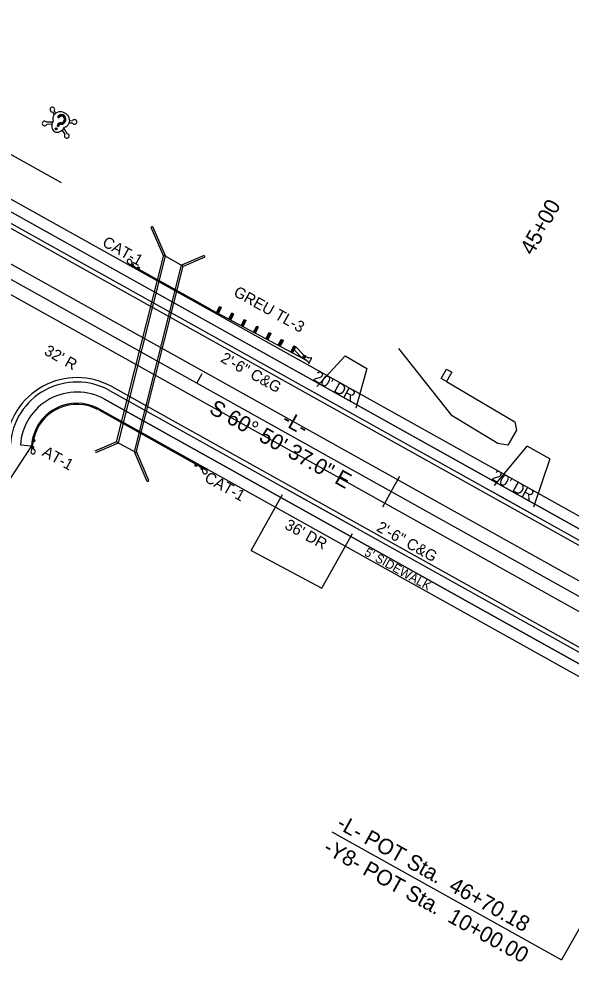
# Model space of a CAD drawing. Extents: x 1762196 to 1766326, y 709922 to 713142.
# Drawn here: x 1764729.9 to 1764978, y 710574.1 to 710998.1 of the extents above; entities that cross this region are included whole.
import ezdxf

# ---------------------------------------------------------------- set-up
doc = ezdxf.new("R2010")
doc.units = 0
for name, color, linetype in [('Culvert Barrel', 7, 'Continuous'), ('Culvert Wing', 7, 'Continuous'), ('Old_Level_20', 7, 'Continuous'), ('Old_Level_3', 7, 'Continuous'), ('Pattern 1', 7, 'Continuous'), ('Pattern 2', 7, 'Continuous'), ('Pattern 4', 7, 'Continuous'), ('Prop Conc 2ft 6in Curb and Gutter', 7, 'Continuous'), ('Prop Dimension', 7, 'Continuous'), ('Prop EOT', 7, 'Continuous'), ('Prop GRAU CAT1 Cell', 7, 'Continuous'), ('Prop Guardrail', 7, 'Continuous'), ('Prop Guardrail Anchor Unit CELL', 7, 'Continuous'), ('Prop Horizontal Alignment', 7, 'Continuous'), ('Prop Horizontal Alignment Direction Label', 7, 'Continuous'), ('Prop Horizontal Alignment Station Label', 7, 'Continuous'), ('Prop Horizontal Alignment Tick Label', 7, 'Continuous'), ('Prop Horizontal Alignment Tick Large', 7, 'Continuous'), ('Prop Horizontal Alignment Tick Small', 7, 'Continuous'), ('Prop Lane Lines', 7, 'Continuous')]:
    doc.layers.add(name, color=color, linetype=linetype)

msp = doc.modelspace()

# ---------------------------------------------------------------- linework, layer by layer
at = {"layer": 'Culvert Barrel'}
for p, q in [((1764773.88, 710808.01), (1764795.03, 710891.88)), ((1764774.63, 710807.59), (1764795.79, 710891.46)), ((1764795.03, 710891.88), (1764803.77, 710887)), ((1764781.87, 710803.55), (1764803.02, 710887.42)), ((1764782.62, 710803.13), (1764803.77, 710887)), ((1764773.88, 710808.01), (1764782.62, 710803.13))]:
    msp.add_line(p, q, dxfattribs=at)
at = {"layer": 'Culvert Wing'}
for p, q in [((1764790.04, 710904.77), (1764789.28, 710904.44)), ((1764789.28, 710904.44), (1764794.91, 710891.39)), ((1764790.04, 710904.77), (1764795.79, 710891.46)), ((1764813.12, 710891.78), (1764803.02, 710887.42)), ((1764813.45, 710891.02), (1764803.73, 710886.82)), ((1764813.45, 710891.02), (1764813.12, 710891.78)), ((1764764.2, 710803.99), (1764773.92, 710808.19)), ((1764764.53, 710803.23), (1764774.63, 710807.59)), ((1764787.61, 710790.24), (1764781.87, 710803.55)), ((1764788.38, 710790.57), (1764782.74, 710803.62)), ((1764787.61, 710790.24), (1764788.38, 710790.57))]:
    msp.add_line(p, q, dxfattribs=at)
at = {"layer": 'Old_Level_20'}
for p, q in [((1764924.57, 710819.74), (1764900.69, 710849.89)), ((1764922.09, 710835.18), (1764952.82, 710817)), ((1764945.07, 710807.21), (1764924.57, 710819.74)), ((1764952.82, 710817), (1764953.55, 710813.29)), ((1764953.55, 710813.29), (1764949.61, 710806.53)), ((1764949.61, 710806.53), (1764945.07, 710807.21))]:
    msp.add_line(p, q, dxfattribs=at)
msp.add_lwpolyline([(1764921.99, 710840.61), (1764924.38, 710839.28), (1764922.09, 710835.18), (1764919.7, 710836.51)], close=True, dxfattribs=at)
at = {"layer": 'Old_Level_3'}
for p, q in [((1764749.11, 710924.39), (1764725.72, 710937.41)), ((1764863.85, 710832.9), (1764876.5, 710846.73)), ((1764876.5, 710846.73), (1764886.23, 710840.99)), ((1764886.23, 710840.99), (1764881.32, 710823.15)), ((1764943.66, 710788.37), (1764958.3, 710805.99)), ((1764968.47, 710800.31), (1764958.3, 710805.99)), ((1764968.47, 710800.31), (1764961.13, 710778.63)), ((1764834.31, 710759.08), (1764848.37, 710784.28)), ((1764866.1, 710742.17), (1764879.81, 710766.74)), ((1764834.31, 710759.08), (1764866.1, 710742.17))]:
    msp.add_line(p, q, dxfattribs=at)
at = {"layer": 'Pattern 1'}
for p, q in [((1764581.02, 710998.13), (1765029.9, 710747.7)), ((1765022.41, 710746.16), (1764578.58, 710993.76)), ((1765087.39, 710649.22), (1764768.48, 710827.13)), ((1764766.04, 710822.76), (1765089.97, 710642.05)), ((1764730.61, 710806.6), (1764735.6, 710806.26))]:
    msp.add_line(p, q, dxfattribs=at)
for radius in [25.5, 20.5]:
    msp.add_arc((1764756.05, 710804.86), radius, 60.8436, 176.081, dxfattribs=at)
at = {"layer": 'Pattern 2'}
for p, q in [((1764581.02, 710998.13), (1765029.9, 710747.7)), ((1764578.58, 710993.76), (1765022.41, 710746.16)), ((1764768.48, 710827.13), (1765087.39, 710649.22)), ((1764766.04, 710822.76), (1765089.97, 710642.05)), ((1764730.61, 710806.6), (1764735.6, 710806.26))]:
    msp.add_line(p, q, dxfattribs=at)
for radius in [25.5, 20.5]:
    msp.add_arc((1764756.05, 710804.86), radius, 60.8436, 176.081, dxfattribs=at)
at = {"layer": 'Pattern 4'}
for p, q in [((1764862.39, 710830.27), (1764879.86, 710820.53)), ((1764881.27, 710769.36), (1764849.83, 710786.9)), ((1764942.2, 710785.75), (1764959.66, 710776.01))]:
    msp.add_line(p, q, dxfattribs=at)
at = {"layer": 'Prop Conc 2ft 6in Curb and Gutter'}
for p, q in [((1764576.39, 710989.83), (1765006.92, 710749.64)), ((1764770.67, 710831.06), (1765076.08, 710660.67))]:
    msp.add_line(p, q, dxfattribs=at)
msp.add_arc((1764756.05, 710804.86), 30, 60.8436, 176.081, dxfattribs=at)
at = {"layer": 'Prop Dimension'}
for p, q in [((1764745.01, 710956.3), (1764745.76, 710954.95)), ((1764745.87, 710956.77), (1764746.47, 710955.67)), ((1764745.1, 710951.76), (1764742.4, 710951.62)), ((1764744.8, 710950.77), (1764742.45, 710950.65)), ((1764747.35, 710950.49), (1764747.09, 710950.02)), ((1764747.09, 710950.02), (1764747.63, 710949.72)), ((1764747.43, 710950.45), (1764747.17, 710949.98)), ((1764747.51, 710950.41), (1764747.24, 710949.93)), ((1764747.3, 710953.88), (1764747.84, 710953.58)), ((1764747.59, 710950.37), (1764747.32, 710949.89)), ((1764747.66, 710950.32), (1764747.4, 710949.85)), ((1764747.74, 710950.28), (1764747.48, 710949.8)), ((1764747.82, 710950.24), (1764747.55, 710949.76)), ((1764747.9, 710950.19), (1764747.63, 710949.72)), ((1764748.39, 710951.71), (1764748.39, 710951.71)), ((1764754.07, 710951.25), (1764752.52, 710951.17)), ((1764754.02, 710952.23), (1764752.77, 710952.16)), ((1764749.47, 710948.16), (1764750.6, 710946.1)), ((1764750.16, 710948.94), (1764751.46, 710946.57)), ((1764735.6, 710806.26), (1764682.91, 710725.7))]:
    msp.add_line(p, q, dxfattribs=at)
for radius in [0.443, 0.345, 0.244, 0.146, 0.0472]:
    msp.add_circle((1764746.72, 710948.68), radius, dxfattribs=at)
for centre, start, end in [((1764745, 710957.34), 326.7494, 270.6579), ((1764741.51, 710951.08), 31.0456, 334.9541), ((1764754.96, 710951.79), 211.0456, 154.9541), ((1764751.47, 710945.53), 146.7494, 90.6579)]:
    msp.add_arc(centre, 1.04, start, end, dxfattribs=at)
for centre, major_axis, ratio, start_param, end_param in [((1764748.99, 710952.79), (3.4, -1.89), 0.885014, 5.564242, 10.143721), ((1764749.05, 710952.9), (1.09, 1.95), 0.9, 3.567618, 7.853982), ((1764749.05, 710952.9), (1.04, 1.86), 0.9, 3.567618, 7.853982), ((1764749.05, 710952.9), (0.99, 1.78), 0.9, 3.567618, 7.853982), ((1764749.05, 710952.9), (0.94, 1.69), 0.9, 3.567618, 7.853982), ((1764749.05, 710952.9), (0.9, 1.6), 0.9, 3.567618, 7.853982), ((1764749.05, 710952.9), (0.85, 1.52), 0.9, 3.567618, 7.853982), ((1764749.05, 710952.9), (0.8, 1.43), 0.9, 3.567618, 7.853982), ((1764749.05, 710952.9), (0.75, 1.35), 0.9, 3.567618, 7.853982), ((1764747.9, 710950.84), (-1.89, -3.4), 0.752542, 4.722735, 7.843636), ((1764748.67, 710949.76), (0.82, 1.46), 0.9, 0.426026, 1.570796), ((1764748.67, 710949.76), (0.77, 1.38), 0.9, 0.426026, 1.570796), ((1764748.67, 710949.76), (0.72, 1.29), 0.9, 0.426026, 1.570796), ((1764748.67, 710949.76), (0.67, 1.2), 0.9, 0.426026, 1.570796), ((1764748.67, 710949.76), (0.62, 1.12), 0.9, 0.426026, 1.570796), ((1764748.67, 710949.76), (0.58, 1.03), 0.9, 0.426026, 1.570796), ((1764748.67, 710949.76), (0.527, 0.946), 0.9, 0.426026, 1.570796), ((1764748.67, 710949.76), (0.479, 0.86), 0.9, 0.426026, 1.570796)]:
    msp.add_ellipse(centre, major_axis=major_axis, ratio=ratio, start_param=start_param, end_param=end_param, dxfattribs=at)
at = {"layer": 'Prop EOT'}
for p, q in [((1764575.41, 710988.08), (1765005.95, 710747.9)), ((1764771.64, 710832.81), (1765077.06, 710662.42))]:
    msp.add_line(p, q, dxfattribs=at)
msp.add_arc((1764756.05, 710804.86), 32, 60.8436, 176.081, dxfattribs=at)
at = {"layer": 'Prop GRAU CAT1 Cell'}
for p, q in [((1764780.58, 710887.36), (1764779.08, 710888.2)), ((1764780.35, 710887.49), (1764780.75, 710888.2)), ((1764780.35, 710887.49), (1764781.36, 710887.86)), ((1764780.96, 710887.15), (1764780.35, 710887.49)), ((1764780.47, 710887.43), (1764780.58, 710887.36)), ((1764780.55, 710889.2), (1764780.7, 710888.11)), ((1764783.68, 710885.64), (1764780.58, 710887.36)), ((1764780.75, 710888.2), (1764781.36, 710887.86)), ((1764780.96, 710887.15), (1764780.75, 710888.2)), ((1764780.86, 710887.67), (1764782.32, 710886.4)), ((1764781.36, 710887.86), (1764780.96, 710887.15)), ((1764783.07, 710885.98), (1764783.46, 710886.68)), ((1764783.07, 710885.98), (1764784.07, 710886.34)), ((1764783.46, 710886.68), (1764784.07, 710886.34)), ((1764783.68, 710885.64), (1764783.46, 710886.68)), ((1764784.07, 710886.34), (1764783.68, 710885.64)), ((1764783.68, 710885.64), (1764783.07, 710885.98)), ((1764809.07, 710797.26), (1764809.46, 710797.97)), ((1764810.07, 710797.63), (1764809.07, 710797.26)), ((1764809.68, 710796.92), (1764809.07, 710797.26)), ((1764809.46, 710797.97), (1764812.56, 710796.24)), ((1764809.46, 710797.97), (1764810.07, 710797.63)), ((1764809.46, 710797.97), (1764809.68, 710796.92)), ((1764810.07, 710797.63), (1764809.68, 710796.92)), ((1764812.29, 710795.93), (1764810.82, 710797.21)), ((1764811.78, 710795.75), (1764812.18, 710796.45)), ((1764812.79, 710796.11), (1764811.78, 710795.75)), ((1764812.4, 710795.41), (1764811.78, 710795.75)), ((1764812.18, 710796.45), (1764812.79, 710796.11)), ((1764812.18, 710796.45), (1764812.4, 710795.41)), ((1764812.79, 710796.11), (1764812.4, 710795.41)), ((1764812.59, 710794.41), (1764812.44, 710795.5)), ((1764812.67, 710796.18), (1764812.56, 710796.24)), ((1764812.56, 710796.24), (1764814.06, 710795.4))]:
    msp.add_line(p, q, dxfattribs=at)
for centre, major_axis in [((1764779.57, 710889.07), (-0.484, -0.867)), ((1764813.57, 710794.54), (0.484, 0.867))]:
    msp.add_ellipse(centre, major_axis=major_axis, ratio=0.995379, start_param=2.210226, end_param=6.283185, dxfattribs=at)
at = {"layer": 'Prop Guardrail'}
for p, q in [((1764816.43, 710867.37), (1764783.68, 710885.64)), ((1764765.8, 710822.33), (1764809.46, 710797.97))]:
    msp.add_line(p, q, dxfattribs=at)
msp.add_arc((1764756.05, 710804.86), 20, 60.8436, 168.2733, dxfattribs=at)
at = {"layer": 'Prop Guardrail Anchor Unit CELL'}
for p, q in [((1764816.43, 710867.37), (1764857.7, 710845.41)), ((1764818.67, 710866.17), (1764820.08, 710868.82)), ((1764820.26, 710867.03), (1764818.67, 710866.17)), ((1764818.67, 710866.17), (1764819.56, 710865.7)), ((1764820.96, 710868.35), (1764819.38, 710867.5)), ((1764819.38, 710867.5), (1764820.26, 710867.03)), ((1764819.38, 710867.5), (1764819.56, 710865.7)), ((1764819.56, 710865.7), (1764820.96, 710868.35)), ((1764819.56, 710865.7), (1764820.26, 710867.03)), ((1764820.26, 710867.03), (1764820.08, 710868.82)), ((1764820.08, 710868.82), (1764820.96, 710868.35)), ((1764824.24, 710863.21), (1764825.67, 710865.91)), ((1764826.55, 710865.44), (1764824.95, 710864.56)), ((1764825.12, 710862.74), (1764826.55, 710865.44)), ((1764825.84, 710864.09), (1764825.67, 710865.91)), ((1764825.67, 710865.91), (1764826.55, 710865.44)), ((1764824.24, 710863.21), (1764825.84, 710864.09)), ((1764824.95, 710864.56), (1764825.84, 710864.09)), ((1764824.95, 710864.56), (1764825.12, 710862.74)), ((1764829.8, 710860.25), (1764831.23, 710862.95)), ((1764829.8, 710860.25), (1764831.4, 710861.13)), ((1764832.11, 710862.48), (1764830.52, 710861.6)), ((1764830.52, 710861.6), (1764831.4, 710861.13)), ((1764830.52, 710861.6), (1764830.68, 710859.78)), ((1764830.68, 710859.78), (1764832.11, 710862.48)), ((1764831.4, 710861.13), (1764831.23, 710862.95)), ((1764831.23, 710862.95), (1764832.11, 710862.48)), ((1764835.36, 710857.3), (1764836.79, 710859.98)), ((1764835.36, 710857.3), (1764836.96, 710858.17)), ((1764835.36, 710857.3), (1764836.25, 710856.83)), ((1764837.67, 710859.51), (1764836.08, 710858.64)), ((1764836.08, 710858.64), (1764836.96, 710858.17)), ((1764836.08, 710858.64), (1764836.25, 710856.83)), ((1764836.25, 710856.83), (1764837.67, 710859.51)), ((1764836.96, 710858.17), (1764836.79, 710859.98)), ((1764836.79, 710859.98), (1764837.67, 710859.51)), ((1764840.93, 710854.34), (1764842.4, 710857.11)), ((1764843.28, 710856.64), (1764841.66, 710855.72)), ((1764841.81, 710853.87), (1764843.28, 710856.64)), ((1764842.54, 710855.25), (1764842.4, 710857.11)), ((1764842.4, 710857.11), (1764843.28, 710856.64)), ((1764840.93, 710854.34), (1764842.54, 710855.25)), ((1764841.66, 710855.72), (1764842.54, 710855.25)), ((1764841.66, 710855.72), (1764841.81, 710853.87)), ((1764846.49, 710851.38), (1764847.9, 710854.02)), ((1764846.49, 710851.38), (1764848.08, 710852.23)), ((1764848.78, 710853.56), (1764847.19, 710852.7)), ((1764847.19, 710852.7), (1764848.08, 710852.23)), ((1764847.19, 710852.7), (1764847.37, 710850.91)), ((1764847.37, 710850.91), (1764848.78, 710853.56)), ((1764848.08, 710852.23), (1764847.9, 710854.02)), ((1764847.9, 710854.02), (1764848.78, 710853.56)), ((1764852.05, 710848.42), (1764853.49, 710851.12)), ((1764852.05, 710848.42), (1764853.65, 710849.3)), ((1764854.37, 710850.65), (1764852.77, 710849.77)), ((1764852.77, 710849.77), (1764853.65, 710849.3)), ((1764852.77, 710849.77), (1764852.93, 710847.95)), ((1764852.93, 710847.95), (1764854.37, 710850.65)), ((1764853.65, 710849.3), (1764853.49, 710851.12)), ((1764853.49, 710851.12), (1764854.37, 710850.65)), ((1764853.65, 710849.3), (1764857.26, 710845.65)), ((1764854.37, 710850.65), (1764857.97, 710846.97)), ((1764857.26, 710845.65), (1764857.97, 710846.97)), ((1764858.85, 710846.5), (1764857.26, 710845.65)), ((1764858.06, 710846), (1764857.77, 710845.46)), ((1764857.77, 710845.46), (1764859.56, 710844.47)), ((1764857.97, 710846.97), (1764858.41, 710846.74)), ((1764858.14, 710845.18), (1764857.97, 710846.97)), ((1764857.97, 710846.97), (1764858.85, 710846.5)), ((1764858.36, 710846.53), (1764858.06, 710846)), ((1764858.14, 710845.18), (1764858.85, 710846.5)), ((1764860.15, 710845.54), (1764858.36, 710846.53)), ((1764859.56, 710844.47), (1764860.17, 710843.14)), ((1764861.59, 710845.71), (1764860.15, 710845.54)), ((1764860.17, 710843.14), (1764861.59, 710845.71)), ((1764735.85, 710805.95), (1764735.71, 710805.26)), ((1764735.71, 710805.26), (1764736.64, 710805.78)), ((1764736.47, 710808.93), (1764735.75, 710805.46)), ((1764736.64, 710805.78), (1764735.85, 710805.95)), ((1764735.85, 710805.95), (1764736.5, 710805.1)), ((1764736.47, 710808.93), (1764736.33, 710808.24)), ((1764736.33, 710808.24), (1764737.26, 710808.76)), ((1764736.33, 710808.24), (1764737.12, 710808.08)), ((1764737.26, 710808.76), (1764736.47, 710808.93)), ((1764736.47, 710808.93), (1764737.12, 710808.08)), ((1764736.5, 710805.1), (1764736.64, 710805.78)), ((1764737.12, 710808.08), (1764737.26, 710808.76)), ((1764735.75, 710805.46), (1764735.4, 710803.77)), ((1764735.71, 710805.26), (1764736.06, 710805.19)), ((1764735.71, 710805.26), (1764736.06, 710805.19)), ((1764735.71, 710805.26), (1764736.5, 710805.1)), ((1764735.74, 710805.39), (1764735.76, 710805.52)), ((1764735.74, 710805.39), (1764735.76, 710805.52)), ((1764737.11, 710804.23), (1764736.32, 710805.14))]:
    msp.add_line(p, q, dxfattribs=at)
msp.add_ellipse((1764736.37, 710803.57), major_axis=(0.972, -0.202), ratio=0.995379, start_param=3.141593, end_param=7.214552, dxfattribs=at)
at = {"layer": 'Prop Horizontal Alignment'}
msp.add_line((1764565.67, 710970.62), (1765117.06, 710663.01), dxfattribs=at)
at = {"layer": 'Prop Horizontal Alignment Station Label'}
for p in [(1765045.86, 710702.73), (1764870.54, 710632.62)]:
    msp.add_line(p, (1764973.73, 710575.16), dxfattribs=at)
at = {"layer": 'Prop Horizontal Alignment Tick Large'}
for q in [(1764901.14, 710792.62), (1764901.14, 710792.62), (1764893.35, 710778.65), (1764893.35, 710778.65)]:
    msp.add_line((1764897.25, 710785.64), q, dxfattribs=at)
at = {"layer": 'Prop Horizontal Alignment Tick Small'}
msp.add_line((1764809.92, 710834.36), (1764812.35, 710838.72), dxfattribs=at)
msp.add_line((1764809.92, 710834.36), (1764812.35, 710838.72), dxfattribs=at)
at = {"layer": 'Prop Lane Lines'}
for p, q in [((1764568.59, 710975.86), (1765119.98, 710668.25)), ((1764562.75, 710965.38), (1765114.14, 710657.77))]:
    msp.add_line(p, q, dxfattribs=at)

# ---------------------------------------------------------------- texts
at = {"layer": 'Prop Dimension'}
for s, height, rotation, p in [("32' R", 5, 330.8875, (1764740.89, 710847.51)), ('2\'-6" C&G', 5, 330.8886, (1764820.18, 710844.21)), ("20' DR", 5, 331.0708, (1764861.74, 710835.87)), ("20' DR", 5, 331.0708, (1764941.97, 710791.22)), ("36' DR", 5, 331.0708, (1764848.96, 710769.2)), ('2\'-6" C&G', 5, 330.8886, (1764890.2, 710768.2)), ("5' SIDEWALK", 4, 330.8354, (1764884.81, 710757.18))]:
    msp.add_text(s, height=height, rotation=rotation, dxfattribs=at).set_placement(p)
at = {"layer": 'Prop Guardrail Anchor Unit CELL'}
for s, p in [('CAT-1', (1764767.03, 710896.3)), ('GREU TL-3', (1764825.99, 710873.91)), ('AT-1', (1764740.02, 710802.04)), ('CAT-1', (1764812.9, 710790.47))]:
    msp.add_text(s, height=5, rotation=330.8436, dxfattribs=at).set_placement(p)
at = {"layer": 'Prop Horizontal Alignment Direction Label'}
for s, p in [('S 60%%d 50\' 37.0" E', (1764814.93, 710821.2)), ('-L-', (1764847.55, 710816.23))]:
    msp.add_text(s, height=7, rotation=330.8436, dxfattribs=at).set_placement(p)
at = {"layer": 'Prop Horizontal Alignment Station Label'}
for s, p in [('-L- POT Sta.  46+70.18', (1764872.17, 710634.66)), ('-Y8- POT Sta.  10+00.00', (1764866.18, 710623.72))]:
    msp.add_text(s, height=7, rotation=330.8875, dxfattribs=at).set_placement(p)
at = {"layer": 'Prop Horizontal Alignment Tick Label'}
msp.add_text('45+00', height=7, rotation=60.8436, dxfattribs=at).set_placement((1764960.79, 710891.48))

doc.saveas('drawing.dxf')
